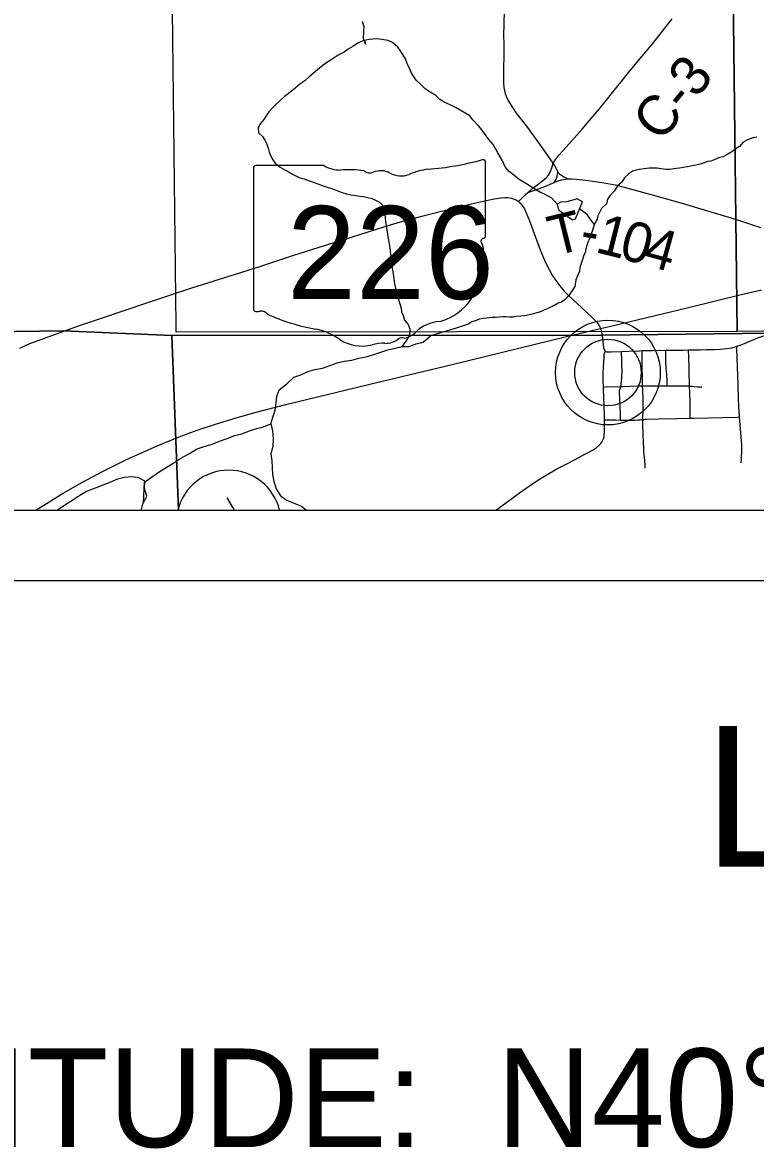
# Model space of a CAD drawing. Extents: x 0 to 34, y 0 to 22.
# Drawn here: x 3.459 to 4.5, y 13.194 to 14.792 of the extents above; entities that cross this region are included whole.
import ezdxf

# ---------------------------------------------------------------- set-up
doc = ezdxf.new("R2010")
doc.units = 0
for name, color, linetype in [('Default', 7, 'Continuous'), ('GM_X_County_Road', 7, 'Continuous'), ('GM_X_County_Road_Text', 7, 'Continuous'), ('GM_X_Major_Lake', 7, 'Continuous'), ('GM_X_Minor_Lake', 7, 'Continuous'), ('GM_X_Minor_River', 7, 'Continuous'), ('GM_X_Rail_Line', 7, 'Continuous'), ('GM_X_Section', 7, 'Continuous'), ('GM_X_State_Location', 7, 'Continuous'), ('GM_X_State_Route', 7, 'Continuous'), ('GM_X_State_Shield', 7, 'Continuous'), ('GM_X_Township_Road', 7, 'Continuous'), ('GM_X_Township_Road_Text', 7, 'Continuous'), ('GM_X_Unincorporated', 7, 'Continuous'), ('GM_X_Unincorporated_Location', 7, 'Continuous'), ('SH_Cut_Line', 7, 'Continuous'), ('SH_Data', 7, 'Continuous'), ('SH_Text', 7, 'Continuous')]:
    doc.layers.add(name, color=color, linetype=linetype)

msp = doc.modelspace()

# ---------------------------------------------------------------- linework, layer by layer
at = {"layer": 'Default'}
msp.add_line((3.6794, 14.1), (3.824, 14.1), dxfattribs=at)
for points in [[(2.6231, 17.3771), (2.6332, 16.3685), (2.6388, 15.4856), (2.6428, 15.3713), (2.6434, 15.3487), (2.6607, 14.3625), (2.7339, 14.3605), (3.1736, 14.3499), (3.5171, 14.3547), (3.6708, 14.3479), (4.282, 14.3483), (4.5209, 14.3512)], [(4.5209, 14.3512), (4.282, 14.3483), (3.6708, 14.3479), (3.6803, 14.1), (8.9, 14.1)]]:
    msp.add_lwpolyline(points, dxfattribs=at)
msp.add_lwpolyline([(2.1, 14.3539), (2.1, 14.1), (3.6803, 14.1), (3.6708, 14.3479), (3.5171, 14.3547), (3.1736, 14.3499), (2.7339, 14.3605), (2.6607, 14.3625), (2.1651, 14.3567)], close=True, dxfattribs=at)
msp.add_arc((3.7517, 14.0824), 0.0744, 13.6542, 166.3458, dxfattribs=at)
at = {"layer": 'GM_X_County_Road'}
for points in [[(4.2127, 14.5925), (4.1959, 14.6164), (4.1849, 14.6315), (4.1751, 14.6449), (4.1606, 14.6638), (4.1552, 14.6714), (4.1518, 14.6767), (4.1487, 14.6821), (4.1462, 14.6873), (4.1448, 14.6912), (4.1438, 14.6956), (4.143, 14.7), (4.1425, 14.7065), (4.1426, 14.7251), (4.1428, 14.747), (4.1429, 14.7628), (4.1427, 14.7736), (4.1433, 14.8086)], [(4.2127, 14.5925), (4.2145, 14.5957), (4.216, 14.5979), (4.2179, 14.6004), (4.2208, 14.6038), (4.231, 14.6154), (4.2536, 14.641), (4.2638, 14.6528), (4.2779, 14.6694), (4.2897, 14.6839), (4.2967, 14.6929), (4.3092, 14.7082), (4.3203, 14.7217), (4.3337, 14.7383), (4.354, 14.7627), (4.3814, 14.7973)], [(4.1764, 14.5508), (4.18, 14.5539), (4.1844, 14.5575), (4.1907, 14.5624), (4.1978, 14.568), (4.2009, 14.5703), (4.2028, 14.572), (4.2044, 14.5737), (4.2061, 14.5758), (4.2076, 14.5781), (4.2094, 14.5821), (4.2107, 14.5858), (4.2127, 14.5925)], [(4.1633, 14.5382), (4.1675, 14.5423), (4.1733, 14.548), (4.1764, 14.5508)], [(4.2841, 14.2748), (4.2836, 14.2847), (4.2836, 14.2935), (4.2842, 14.304), (4.2849, 14.3167), (4.2852, 14.3209), (4.2858, 14.3238), (4.2866, 14.3257)], [(4.2855, 14.2281), (4.2853, 14.2339), (4.2851, 14.2481), (4.2846, 14.261), (4.2843, 14.2712), (4.2841, 14.2748)], [(4.131, 14.1), (4.1451, 14.11), (4.165, 14.1245), (4.179, 14.1346), (4.1908, 14.1424), (4.2026, 14.1498), (4.218, 14.1585), (4.2337, 14.1667), (4.25, 14.1754), (4.2575, 14.1794), (4.2633, 14.1825), (4.2685, 14.1853), (4.2732, 14.1882), (4.2757, 14.1903), (4.2779, 14.1924), (4.2803, 14.1947), (4.2824, 14.1976), (4.2836, 14.2002), (4.2844, 14.2024), (4.2849, 14.2048), (4.2852, 14.2072), (4.2853, 14.2097), (4.2856, 14.2137), (4.2856, 14.2214), (4.2855, 14.2281)]]:
    msp.add_lwpolyline(points, dxfattribs=at)
at = {"layer": 'GM_X_Major_Lake'}
for points in [[(3.6305, 14.1106), (3.6354, 14.1201), (3.6323, 14.1307), (3.6326, 14.141), (3.6231, 14.1466), (3.6136, 14.1473), (3.6037, 14.1465), (3.5935, 14.1441), (3.583, 14.1395), (3.5731, 14.1357), (3.5618, 14.1311), (3.5505, 14.1268), (3.5403, 14.1207), (3.5305, 14.1142), (3.5203, 14.108), (3.5097, 14.1008), (3.5086, 14.1)], [(3.6275, 14.1), (3.6276, 14.1008), (3.6301, 14.1106), (3.6305, 14.1106)]]:
    msp.add_lwpolyline(points, dxfattribs=at)
at = {"layer": 'GM_X_Minor_Lake'}
for points in [[(4.2541, 14.5378), (4.2469, 14.5419), (4.2404, 14.54), (4.2317, 14.5377), (4.2234, 14.5373), (4.2181, 14.5342), (4.2204, 14.5263), (4.2402, 14.5123), (4.2443, 14.5134)], [(4.2443, 14.5134), (4.2541, 14.5378)]]:
    msp.add_lwpolyline(points, dxfattribs=at)
at = {"layer": 'GM_X_Minor_River'}
for points in [[(3.9447, 14.7668), (3.9461, 14.7616), (3.9434, 14.7696), (3.9438, 14.7802), (3.9442, 14.7867), (3.9418, 14.7932)], [(4.2181, 14.5342), (4.2101, 14.5432), (4.2056, 14.546), (4.2004, 14.5485), (4.1947, 14.5508), (4.1855, 14.5561), (4.1759, 14.5622), (4.1691, 14.5664), (4.1641, 14.5695), (4.1568, 14.5756), (4.1503, 14.5809), (4.1446, 14.5874), (4.1404, 14.5961), (4.1342, 14.6075), (4.1273, 14.6189), (4.1212, 14.6261), (4.1151, 14.6349), (4.1113, 14.6398), (4.1071, 14.6452), (4.0986, 14.6543), (4.094, 14.6596), (4.0746, 14.671), (4.0665, 14.6752), (4.0577, 14.6794), (4.0516, 14.6832), (4.0459, 14.6885), (4.0379, 14.6935), (4.031, 14.6981), (4.0249, 14.7038), (4.018, 14.7106), (4.0115, 14.7205), (4.0084, 14.727), (4.0053, 14.7342), (4.003, 14.7407), (3.9992, 14.7467), (3.9954, 14.7525), (3.9919, 14.7574), (3.9843, 14.7639), (3.9782, 14.7669), (3.9629, 14.7692), (3.9568, 14.7688), (3.9514, 14.7684), (3.9423, 14.7662), (3.935, 14.7628), (3.9278, 14.7582), (3.9213, 14.7544), (3.9156, 14.7502), (3.9072, 14.7457), (3.8973, 14.7392), (3.8908, 14.735), (3.8859, 14.7316), (3.8779, 14.7251), (3.8718, 14.7198), (3.8661, 14.7153), (3.8596, 14.7096), (3.8528, 14.7046), (3.8459, 14.6989), (3.836, 14.6909), (3.831, 14.6871), (3.825, 14.6814), (3.8185, 14.6757), (3.8135, 14.6708), (3.8086, 14.6655), (3.8048, 14.6598), (3.8014, 14.6548), (3.7968, 14.6488), (3.7937, 14.6434), (3.7941, 14.6358), (3.7995, 14.6305), (3.8029, 14.6252), (3.806, 14.6195), (3.8076, 14.6138), (3.8091, 14.6084), (3.8114, 14.6027), (3.8145, 14.5974), (3.8175, 14.5925), (3.8248, 14.5868), (3.8313, 14.583), (3.8374, 14.5799), (3.8435, 14.5765), (3.8519, 14.5723), (3.8584, 14.5704), (3.8634, 14.5685), (3.8695, 14.5666), (3.8806, 14.5624), (3.8871, 14.5601), (3.902, 14.5552), (3.9077, 14.5529), (3.913, 14.551), (3.9191, 14.5491)], [(4.5021, 14.6294), (4.4964, 14.6286), (4.4887, 14.6256), (4.4822, 14.6221), (4.4773, 14.6164), (4.4712, 14.6126), (4.4666, 14.6088), (4.4609, 14.6054), (4.4541, 14.6016), (4.4491, 14.6005), (4.4415, 14.5975), (4.4365, 14.5956), (4.4319, 14.5948), (4.427, 14.5933), (4.4213, 14.5914), (4.4129, 14.5895), (4.4079, 14.5883), (4.4033, 14.5872), (4.3972, 14.5865), (4.3919, 14.5857), (4.3873, 14.5849), (4.3778, 14.5838), (4.3728, 14.5838), (4.3659, 14.5846), (4.3602, 14.5853), (4.3491, 14.5853), (4.3419, 14.5846), (4.3346, 14.5834), (4.3255, 14.5812), (4.3202, 14.5774), (4.3137, 14.5717), (4.3099, 14.5656), (4.3042, 14.5603), (4.2992, 14.553), (4.2931, 14.5462), (4.2893, 14.5405), (4.2886, 14.5352), (4.2814, 14.5283), (4.2787, 14.5234), (4.276, 14.5177), (4.2753, 14.5131), (4.2719, 14.5074), (4.27, 14.5021), (4.2685, 14.4972), (4.2654, 14.4896), (4.2643, 14.485), (4.2616, 14.4804), (4.259, 14.4709), (4.2582, 14.466), (4.2556, 14.4607), (4.2544, 14.4557), (4.2525, 14.4504), (4.2506, 14.4447), (4.2499, 14.4394), (4.2472, 14.4329), (4.245, 14.4268), (4.2434, 14.4177), (4.2385, 14.4105), (4.2355, 14.4052), (4.2301, 14.3995), (4.2244, 14.3953), (4.2195, 14.3938), (4.2141, 14.3904), (4.2042, 14.3858), (4.1993, 14.3839), (4.1947, 14.3816), (4.1893, 14.3801), (4.1829, 14.3782), (4.1764, 14.3767), (4.1718, 14.3759), (4.1665, 14.3752), (4.1604, 14.3748)], [(3.9191, 14.5491), (3.9252, 14.5475), (3.9325, 14.5468), (3.9382, 14.546), (3.9432, 14.5453), (3.9489, 14.5437), (3.9539, 14.543), (3.9592, 14.5407), (3.9661, 14.5373), (3.9707, 14.5323), (3.9722, 14.5266), (3.9734, 14.5201), (3.9738, 14.5148), (3.9746, 14.5091), (3.9753, 14.5042), (3.9761, 14.4981), (3.9773, 14.492), (3.9781, 14.4855), (3.9796, 14.4783), (3.9804, 14.4726), (3.9812, 14.4673), (3.9823, 14.457), (3.9831, 14.4487), (3.9854, 14.4353), (3.9862, 14.4289), (3.987, 14.4213), (3.9885, 14.4152), (3.9901, 14.4099), (3.9912, 14.4049), (3.9931, 14.3992), (3.9951, 14.3916), (3.9966, 14.3867), (3.997, 14.3817), (3.9997, 14.3764), (4.0016, 14.3696), (4.0066, 14.3635), (4.0089, 14.357), (4.0085, 14.3473)], [(4.2712, 14.5055), (4.2689, 14.5084), (4.2646, 14.5141), (4.2608, 14.5198), (4.2539, 14.5251), (4.2499, 14.5272)], [(4.1604, 14.3748), (4.1558, 14.374), (4.1508, 14.374), (4.1459, 14.3744), (4.1413, 14.3744), (4.1363, 14.374), (4.1306, 14.3733), (4.126, 14.3733), (4.1176, 14.3725), (4.113, 14.3722), (4.1081, 14.371), (4.102, 14.3687), (4.097, 14.3672), (4.0917, 14.3642), (4.0864, 14.3623), (4.0749, 14.3585), (4.0384, 14.3473)], [(3.6305, 14.1106), (3.6322, 14.1398), (3.642, 14.1467), (3.6529, 14.1544), (3.6627, 14.1605), (3.6737, 14.167), (3.6839, 14.1739), (3.6952, 14.18), (3.7069, 14.1869), (3.7167, 14.1904), (3.728, 14.1939), (3.7386, 14.1978), (3.7496, 14.2016), (3.7601, 14.2059), (3.7704, 14.2086), (3.7813, 14.2124), (3.7911, 14.2159), (3.801, 14.2183), (3.8115, 14.2225), (3.8145, 14.232), (3.8175, 14.2419), (3.8189, 14.2517), (3.82, 14.2612), (3.8233, 14.2707), (3.8342, 14.2795), (3.844, 14.2887), (3.8542, 14.2922), (3.864, 14.2968), (3.8739, 14.2995), (3.8848, 14.3018), (3.8954, 14.3053), (3.9056, 14.3092), (3.9158, 14.3115), (3.9268, 14.3131), (3.9366, 14.3158), (3.9469, 14.3178), (3.9578, 14.3209), (3.9676, 14.3243), (3.9778, 14.3274), (3.9881, 14.3302), (3.9979, 14.3325), (4.0054, 14.342), (4.0085, 14.3473)], [(3.9979, 14.3325), (4.0077, 14.3322), (4.0179, 14.336), (4.0278, 14.3387), (4.0384, 14.3473)], [(3.8115, 14.2225), (3.8139, 14.2127), (3.8147, 14.2013), (3.8144, 14.1903), (3.8115, 14.18), (3.8131, 14.1702), (3.8135, 14.1607), (3.814, 14.1508), (3.8159, 14.1406), (3.819, 14.1304), (3.8256, 14.1198), (3.8351, 14.1138), (3.8457, 14.1097), (3.8552, 14.1056), (3.8624, 14.1)]]:
    msp.add_lwpolyline(points, dxfattribs=at)
at = {"layer": 'GM_X_Rail_Line'}
for points in [[(4.2333, 14.3468), (4.2797, 14.3578), (4.2965, 14.3618), (4.405, 14.3879), (4.4779, 14.4056), (4.5085, 14.413)], [(3.4777, 14.1), (3.4778, 14.1), (3.5141, 14.1229), (3.543, 14.1394), (3.5734, 14.1555), (3.6057, 14.1715), (3.6502, 14.1913), (3.6812, 14.2039), (3.707, 14.2134), (3.7328, 14.2222), (3.7625, 14.2312), (3.7908, 14.2391), (3.8329, 14.2498), (3.9659, 14.282), (4.0693, 14.3066), (4.2333, 14.3468)]]:
    msp.add_lwpolyline(points, dxfattribs=at)
at = {"layer": 'GM_X_Section'}
for points in [[(4.4621, 15.354), (5.3765, 15.3766), (5.4966, 15.3772), (5.5053, 14.3671), (4.4738, 14.3535)], [(3.6656, 15.3395), (4.4621, 15.354), (4.4738, 14.3535), (3.6771, 14.3527), (3.677, 14.3622)]]:
    msp.add_lwpolyline(points, close=True, dxfattribs=at)
at = {"layer": 'GM_X_State_Route'}
for points in [[(3.5173, 14.3542), (3.5398, 14.362), (3.5751, 14.3741), (3.6341, 14.394), (3.6696, 14.4058), (3.6992, 14.4154), (3.7615, 14.435), (3.7971, 14.4465), (3.8415, 14.4609), (3.88, 14.4733), (3.9186, 14.4853), (3.9483, 14.4947), (3.972, 14.5021), (3.9959, 14.5092), (4.026, 14.5173), (4.0653, 14.5271), (4.1107, 14.538), (4.129, 14.5419), (4.1383, 14.5434), (4.1446, 14.5438), (4.1478, 14.5437), (4.151, 14.5434), (4.1534, 14.5428), (4.1559, 14.542), (4.1585, 14.5409), (4.1613, 14.5395), (4.1628, 14.5386), (4.1633, 14.5382), (4.1647, 14.537), (4.1662, 14.5356), (4.1683, 14.5332), (4.1701, 14.5306), (4.1717, 14.5279), (4.1744, 14.5222), (4.179, 14.5106), (4.194, 14.4698), (4.1987, 14.4584), (4.2025, 14.4499), (4.2068, 14.4417), (4.2114, 14.4337), (4.2165, 14.4259), (4.222, 14.4185), (4.2279, 14.4114), (4.2343, 14.4048), (4.2595, 14.3817), (4.2685, 14.3731), (4.2729, 14.3686), (4.2749, 14.3662), (4.2768, 14.3636), (4.2779, 14.3619), (4.2788, 14.3603), (4.2796, 14.3585), (4.2807, 14.3549), (4.2817, 14.3506), (4.2822, 14.3478)], [(3.4551, 14.33), (3.4693, 14.3364), (3.5173, 14.3542)], [(4.2822, 14.3478), (4.2835, 14.3347), (4.2842, 14.3303), (4.2849, 14.328), (4.2858, 14.3266), (4.2866, 14.3257), (4.2875, 14.3252), (4.2884, 14.3249), (4.29, 14.3247), (4.2918, 14.3246), (4.2949, 14.3247), (4.3095, 14.3253), (4.3196, 14.3257), (4.335, 14.3264), (4.339, 14.3265), (4.3539, 14.3268), (4.3727, 14.3271), (4.3874, 14.3273), (4.3966, 14.3273), (4.4049, 14.3275), (4.4146, 14.3277), (4.4212, 14.3278), (4.4303, 14.328), (4.442, 14.3282), (4.4504, 14.3287), (4.4591, 14.3295), (4.4658, 14.3305), (4.4712, 14.3318), (4.4736, 14.3326)], [(4.4736, 14.3326), (4.4796, 14.3346), (4.4941, 14.3411), (4.5033, 14.3446), (4.5131, 14.348), (4.5211, 14.3506)]]:
    msp.add_lwpolyline(points, dxfattribs=at)
at = {"layer": 'GM_X_State_Shield'}
for p, q in [((4.1166, 14.4895), (4.1166, 14.5942)), ((3.787, 14.5858), (3.787, 14.3857)), ((3.8868, 14.5892), (3.7903, 14.5892)), ((4.1166, 14.4895), (4.1166, 14.4895))]:
    msp.add_line(p, q, dxfattribs=at)
for centre, major_axis, start_param, end_param in [((3.9992, 14.8621), (0.3495, 0), 4.814394, 5.042369), ((4.1129, 14.5946), (0.00367, 0), 6.141152, 7.989035), ((3.7908, 14.5862), (0.00382, 0), 1.712693, 3.28349), ((3.9098, 14.6125), (0.037, 0), 4.042523, 4.731795), ((3.922, 14.4769), (0.133, 0), 1.404758, 1.657858), ((3.9522, 14.5873), (0.0107, 0), 3.836095, 5.185415), ((3.9679, 14.5641), (0.0222, 0), 0.950623, 2.079405), ((3.9966, 14.5959), (0.0267, 0), 4.081561, 5.145723), ((4.0438, 14.5281), (0.0703, 0), 1.699011, 2.107814), ((4.1157, 14.4818), (0.00568, 0), 1.883978, 3.671073), ((4.1127, 14.4891), (0.00393, 0), 5.05454, 6.418171), ((4.0796, 14.4686), (0.0341, 0), 5.934695, 6.695948), ((4.1297, 14.4457), (0.0248, 0), 2.387724, 3.262537), ((4.0188, 14.4324), (0.0874, 0), 5.101752, 6.440018), ((3.7908, 14.3852), (0.00385, 0), 3.00124, 4.508301), ((3.7914, 14.4057), (0.0294, 0), 4.665946, 4.897461), ((3.7974, 14.3741), (0.0106, 0), 0.519207, 1.627899), ((3.9312, 14.5539), (0.2524, 0), 4.195997, 4.488961), ((3.856, 14.2958), (0.079, 0), 0.823519, 1.323587), ((4.0556, 14.3295), (0.0479, 0), 1.647645, 2.488434), ((3.9414, 14.3731), (0.0501, 0), 4.026481, 4.996735), ((3.974, 14.3582), (0.0267, 0), 4.691044, 5.507374), ((3.9982, 14.3388), (0.00752, 0), 1.147584, 2.315152), ((3.995, 14.3663), (0.0282, 0), 4.937069, 5.64225), ((3.9704, 14.304), (0.0412, 0), 1.495662, 1.94098)]:
    msp.add_ellipse(centre, major_axis=major_axis, ratio=0.8, start_param=start_param, end_param=end_param, dxfattribs=at)
at = {"layer": 'GM_X_Township_Road'}
for points in [[(4.2127, 14.5925), (4.2169, 14.5849), (4.2181, 14.5824), (4.2192, 14.5805)], [(4.2142, 14.5652), (4.2156, 14.5676), (4.2164, 14.5691), (4.2171, 14.5705), (4.2175, 14.5718), (4.2181, 14.5734), (4.2185, 14.5752), (4.2189, 14.5769), (4.219, 14.5785), (4.2192, 14.5805)], [(4.2192, 14.5805), (4.2199, 14.5795), (4.2222, 14.5771), (4.2247, 14.575), (4.2276, 14.5734), (4.2305, 14.572), (4.234, 14.5704)], [(4.1764, 14.5508), (4.1794, 14.5518), (4.1867, 14.5541), (4.1982, 14.5587), (4.2142, 14.5652)], [(4.2142, 14.5652), (4.2184, 14.5669), (4.2243, 14.5689), (4.2273, 14.5696), (4.2304, 14.5701), (4.2323, 14.5703), (4.234, 14.5704)], [(4.234, 14.5704), (4.2397, 14.5704), (4.2458, 14.5698), (4.2588, 14.5684), (4.2716, 14.5666), (4.2849, 14.5646), (4.3005, 14.5619), (4.3133, 14.5585), (4.3343, 14.5528), (4.3582, 14.5461), (4.3822, 14.5397), (4.3972, 14.5354), (4.4269, 14.5265), (4.4507, 14.5193), (4.4656, 14.5149), (4.4775, 14.5111), (4.5069, 14.5011)], [(4.3103, 14.3042), (4.3103, 14.3092), (4.3101, 14.3152), (4.3097, 14.3223), (4.3095, 14.3253)], [(4.3397, 14.2766), (4.3395, 14.2851), (4.339, 14.3067), (4.339, 14.3158), (4.339, 14.3232), (4.339, 14.3265)], [(4.3745, 14.2764), (4.3744, 14.2787), (4.3743, 14.2835), (4.374, 14.2926), (4.3732, 14.3022), (4.3725, 14.3112), (4.3726, 14.3178), (4.3727, 14.3248), (4.3727, 14.3271)], [(4.4063, 14.2762), (4.4062, 14.2788), (4.4061, 14.2836), (4.406, 14.2908), (4.4056, 14.3055), (4.4053, 14.3142), (4.4051, 14.3203), (4.405, 14.3249), (4.4049, 14.3275)], [(4.4775, 14.2323), (4.4773, 14.2344), (4.4769, 14.2396), (4.4764, 14.2467), (4.4758, 14.2592), (4.4752, 14.2777), (4.4737, 14.3293), (4.4736, 14.3326)], [(4.3086, 14.2755), (4.3089, 14.2766), (4.3091, 14.2779), (4.3092, 14.2789), (4.3099, 14.2876), (4.3104, 14.3001), (4.3103, 14.3042)], [(4.2841, 14.2748), (4.2864, 14.2749), (4.3086, 14.2755)], [(4.3083, 14.228), (4.3081, 14.2366), (4.3078, 14.2456), (4.3074, 14.2541), (4.3071, 14.2606), (4.3069, 14.2644), (4.3069, 14.2673), (4.307, 14.2699), (4.3073, 14.2714), (4.3076, 14.2727), (4.3082, 14.2743), (4.3086, 14.2755)], [(4.3086, 14.2755), (4.312, 14.2756), (4.333, 14.2763), (4.3397, 14.2766)], [(4.3397, 14.2766), (4.3453, 14.2765), (4.3697, 14.2764), (4.3745, 14.2764)], [(4.3402, 14.2288), (4.3402, 14.2322), (4.3403, 14.2397), (4.3404, 14.2518), (4.3404, 14.2575), (4.3401, 14.2702), (4.3397, 14.2766)], [(4.3745, 14.2764), (4.3978, 14.2765), (4.4, 14.2765), (4.402, 14.2764), (4.4048, 14.2763), (4.4063, 14.2762)], [(4.4063, 14.2762), (4.4082, 14.2761), (4.4102, 14.2759), (4.4127, 14.2757), (4.4177, 14.2753), (4.4238, 14.275)], [(4.4073, 14.2306), (4.4073, 14.2352), (4.4071, 14.2508), (4.4067, 14.2694), (4.4064, 14.2733), (4.4063, 14.2762)], [(4.2855, 14.2281), (4.288, 14.2281), (4.3017, 14.2281), (4.3083, 14.228)], [(4.3083, 14.228), (4.3169, 14.2279), (4.3291, 14.228), (4.3329, 14.2282), (4.3357, 14.2283), (4.3376, 14.2285), (4.3402, 14.2288)], [(4.3434, 14.1597), (4.3432, 14.1635), (4.3427, 14.1705), (4.342, 14.1787), (4.3416, 14.1832), (4.3412, 14.1881), (4.3407, 14.1971), (4.3403, 14.2066), (4.3401, 14.2235), (4.3402, 14.2288)], [(4.3402, 14.2288), (4.3419, 14.2289), (4.3433, 14.229), (4.3451, 14.2291), (4.3632, 14.2298), (4.3881, 14.2303), (4.4073, 14.2306)], [(4.4073, 14.2306), (4.413, 14.2307), (4.4535, 14.2314), (4.4745, 14.2322), (4.4775, 14.2323)], [(4.4796, 14.1673), (4.4799, 14.172), (4.4803, 14.1763), (4.4806, 14.1822), (4.4808, 14.1866), (4.4806, 14.1923), (4.4802, 14.1978), (4.4775, 14.2323)], [(3.7601, 14.1), (3.7578, 14.1034), (3.7495, 14.1177)]]:
    msp.add_lwpolyline(points, dxfattribs=at)
at = {"layer": 'GM_X_Unincorporated'}
for radius in [0.0744, 0.0472]:
    msp.add_circle((4.2904, 14.2954), radius, dxfattribs=at)
at = {"layer": 'GM_X_Unincorporated_Location'}
msp.add_line((4.2904, 14.2954), (4.2904, 14.2954), dxfattribs=at)
at = {"layer": 'SH_Cut_Line'}
for points in [[(2.6231, 17.3771), (2.6332, 16.3685), (2.6388, 15.4856), (2.6428, 15.3713), (2.6434, 15.3487), (2.6607, 14.3625), (2.7339, 14.3605), (3.1736, 14.3499), (3.5171, 14.3547), (3.6708, 14.3479), (4.282, 14.3483), (4.5209, 14.3512)], [(4.5209, 14.3512), (4.282, 14.3483), (3.6708, 14.3479), (3.5171, 14.3547), (3.1736, 14.3499), (2.7339, 14.3605), (2.6607, 14.3625), (2.1651, 14.3567)], [(2.1, 14.1), (8.9, 14.1)]]:
    msp.add_lwpolyline(points, dxfattribs=at)
at = {"layer": 'SH_Data'}
for p, q in [((2.1, 14.1), (8.9, 14.1)), ((2, 14), (9, 14))]:
    msp.add_line(p, q, dxfattribs=at)

# ---------------------------------------------------------------- texts
at = {"layer": 'GM_X_County_Road_Text'}
msp.add_text('C-3', height=0.05682, rotation=51.1271, dxfattribs=at).set_placement((4.3656, 14.6206))
at = {"layer": 'GM_X_State_Location'}
for s in ['s', 'r']:
    msp.add_text(s, height=0.000189, dxfattribs=at).set_placement((3.9481, 14.4724))
msp.add_text('226', height=0.000189, rotation=0, dxfattribs=at).set_placement((3.8812, 14.4587))
at = {"layer": 'GM_X_State_Shield'}
msp.add_text('226', height=0.13184, dxfattribs=at).set_placement((3.8344, 14.3998))
at = {"layer": 'GM_X_Township_Road_Text'}
for s, rotation, p in [('T', 13.8684, (4.2135, 14.4603)), ('1', 345.818, (4.2705, 14.4668)), ('0', 344.8145, (4.3042, 14.4583)), ('-', 350.8713, (4.2488, 14.4702)), ('4', 344.6636, (4.338, 14.4491))]:
    msp.add_text(s, height=0.0568, rotation=rotation, dxfattribs=at).set_placement(p)
at = {"layer": 'SH_Text'}
for s, height, p in [('LOCATION MAP', 0.2, (4.4269, 13.5937)), ('LATITUDE:  N40°43\'20"     LONGITUDE:  W82°03\'26"', 0.14, (3.071, 13.1958))]:
    msp.add_text(s, height=height, dxfattribs=at).set_placement(p)

doc.saveas('drawing.dxf')
